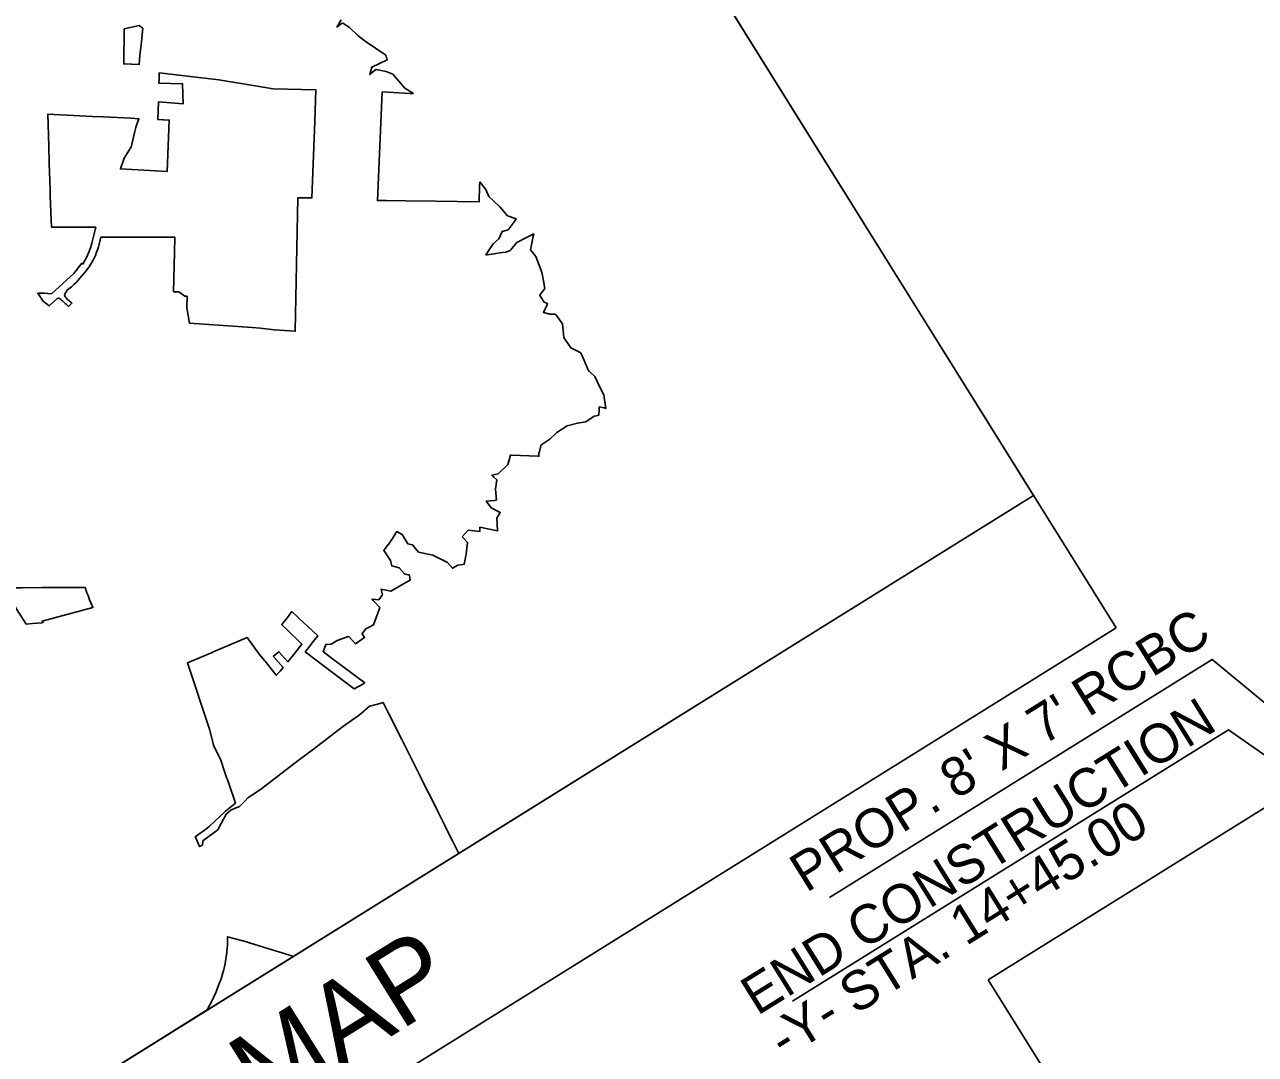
# Model space of a CAD drawing. Extents: x 2038094 to 2053858, y 751760 to 764312.
# Drawn here: x 2044647 to 2046307, y 758364 to 759754 of the extents above; entities that cross this region are included whole.
import ezdxf

# ---------------------------------------------------------------- set-up
doc = ezdxf.new("R2010")
doc.units = 0
for name, color, linetype in [('Old_Level_14', 7, 'Continuous'), ('Prop Shade Light', 7, 'Continuous'), ('Scratch_Level_1', 7, 'Continuous'), ('Sheet Clip Boundary CELL', 7, 'Continuous'), ('Sheet Title CELL', 7, 'Continuous')]:
    doc.layers.add(name, color=color, linetype=linetype)

msp = doc.modelspace()

# ---------------------------------------------------------------- linework, layer by layer
at = {"layer": 'Old_Level_14'}
for points in [[(2046763, 758471.6), (2046248.1, 758896.8), (2045732.1, 758575.3)], [(2046620.1, 758557.1), (2046270.1, 758802), (2045682.1, 758435.8)]]:
    msp.add_lwpolyline(points, dxfattribs=at)
at = {"layer": 'Prop Shade Light'}
for p, q in [((2045009, 758495.9), (2045232.3, 758635)), ((2044650.5, 758272.7), (2044893.1, 758423.7))]:
    msp.add_line(p, q, dxfattribs=at)
for points in [[(2045075.6, 759755.8), (2045067.8, 759750.3), (2045073.7, 759759.9)], [(2044805.2, 759740.4), (2044804.5, 759729.9), (2044802, 759712.2), (2044801.2, 759699.8), (2044780.4, 759700.4), (2044781, 759747.7), (2044801.3, 759752.4), (2044806, 759748.7), (2044805.2, 759740.4)], [(2045171.1, 759660.6), (2045159.3, 759667.9), (2045143.5, 759686.6), (2045134.1, 759690.3), (2045120.5, 759693), (2045113, 759686.9), (2045112.9, 759686.8), (2045112.1, 759686.2), (2045115, 759696.2), (2045135.7, 759705.8), (2045134.6, 759709.4), (2045134.5, 759709.5), (2045133.7, 759712.3), (2045105.8, 759731.2), (2045096.7, 759738.6), (2045084.6, 759750), (2045075.8, 759755.7)], [(2044865.5, 759371.1), (2044865.9, 759387), (2044862.7, 759387.1), (2044854.5, 759393), (2044848.5, 759393.1), (2044847.6, 759393.1), (2044848.9, 759446.1), (2044849.4, 759466.5), (2044749.6, 759466.8), (2044747.2, 759457.4), (2044746.2, 759453.5), (2044744.9, 759449.4), (2044743.8, 759446.4), (2044742.1, 759442.1), (2044739.9, 759437.4), (2044737.9, 759433.6), (2044735.7, 759429.8), (2044733.6, 759426.6), (2044731.6, 759423.8), (2044729.5, 759421.1), (2044718.6, 759408.3), (2044717.3, 759406.6), (2044715.6, 759405), (2044713.2, 759402.6), (2044710.1, 759399.8), (2044704.5, 759395.5), (2044700.3, 759389.5), (2044701.2, 759386.3), (2044702.8, 759384.6), (2044704.7, 759382.6), (2044706.8, 759380.7), (2044708.8, 759379), (2044710.5, 759377.6), (2044705.8, 759373.2), (2044703.2, 759375.6), (2044701.3, 759377.2), (2044700.1, 759378.4), (2044699.4, 759379), (2044698.5, 759379.8), (2044697.6, 759380.6), (2044696.8, 759381.2), (2044696.2, 759381.8), (2044695.8, 759382.2), (2044695.1, 759382.8), (2044694.4, 759383.4), (2044693.8, 759383.9), (2044693.6, 759384.1), (2044693.2, 759384.2), (2044693, 759384.3), (2044692.5, 759384.3), (2044692, 759384.3), (2044691.8, 759384.3), (2044691.4, 759384.1), (2044691.1, 759383.9), (2044690.8, 759383.7), (2044680, 759374), (2044671.9, 759380.4), (2044664.3, 759391.1), (2044669.7, 759391), (2044672.9, 759391), (2044683.1, 759390.3), (2044713, 759417.8), (2044723.9, 759431.5), (2044725.4, 759430.3), (2044728.1, 759435), (2044730.7, 759440.2), (2044733.3, 759446.3), (2044735.4, 759452.3), (2044737.2, 759458.6), (2044742.7, 759480.2), (2044683, 759480.2), (2044681.7, 759511.2), (2044681.3, 759522.3), (2044681, 759531.3), (2044680, 759565.9), (2044679.3, 759589.7), (2044678.9, 759604.2), (2044678, 759632.7), (2044738.1, 759629.7), (2044753, 759628.9), (2044790.4, 759627.2), (2044800.8, 759626.6), (2044799, 759621.3), (2044796.8, 759615.3), (2044796.5, 759614.5), (2044794.9, 759607.7), (2044790.5, 759588.1), (2044790.1, 759587.5), (2044781, 759573.3), (2044775.8, 759558.7), (2044823.4, 759556), (2044838.8, 759555.1), (2044841.8, 759624.6), (2044826.4, 759625.4), (2044827.3, 759649.5), (2044860.5, 759646.5), (2044859.8, 759673.8), (2044827.9, 759674.3), (2044828, 759679.4), (2044828.2, 759688.6)], [(2044828.2, 759688.6), (2044908.4, 759679.1), (2044963, 759669.9), (2044982.1, 759666.8), (2045039.5, 759665.5), (2045038, 759622.6), (2045034.2, 759519.6), (2045015.1, 759519.6), (2045011.6, 759339.8), (2044983.2, 759341.6), (2044965, 759343.9), (2044953.5, 759344.7), (2044869.1, 759350.6), (2044865.5, 759371.1)], [(2045260.4, 759541.4), (2045260.2, 759536.4), (2045259.6, 759514.3), (2045200.6, 759515.2), (2045160.4, 759515.7), (2045134.4, 759516.1), (2045122.5, 759516), (2045128.9, 759662.6), (2045166.5, 759660.6), (2045169.7, 759660.4), (2045171.1, 759660.6)], [(2045280.1, 759111.5), (2045280.2, 759111.5), (2045283, 759111.8), (2045281.9, 759126.8), (2045283.4, 759139.3), (2045279.7, 759142.9), (2045279.7, 759143), (2045277.1, 759145.5), (2045285.5, 759147.5), (2045297.4, 759158.9), (2045297.6, 759159.1), (2045298.4, 759159.8), (2045301.1, 759169.3), (2045301.9, 759172.3), (2045303.2, 759172.3), (2045339.3, 759171.1), (2045339.4, 759171), (2045340.4, 759171), (2045340.3, 759174.6), (2045340.9, 759177.4), (2045342.7, 759184.9), (2045342.9, 759185.9), (2045355, 759194.1), (2045364.5, 759203), (2045378.5, 759212.2), (2045392.2, 759215.8), (2045403.4, 759217.4), (2045414.9, 759224.9), (2045417.5, 759225.6), (2045419.1, 759226.1), (2045419.2, 759226.1), (2045421.2, 759226.7), (2045421.4, 759233.4), (2045421.4, 759235.1), (2045421.5, 759237.7), (2045428.1, 759236.2), (2045428.2, 759236.2), (2045430.7, 759235.6), (2045427.7, 759253.7), (2045422.6, 759264.1), (2045415.6, 759278.5), (2045408.6, 759285.5), (2045406.3, 759287.9), (2045404.7, 759292), (2045403.9, 759294), (2045400.3, 759302.5), (2045396.8, 759310.7), (2045383.4, 759317.5), (2045374, 759331.3), (2045372, 759349.6), (2045362.5, 759362.7), (2045354.9, 759362.8), (2045346.5, 759365.1), (2045346.3, 759365.1), (2045347.9, 759368.3), (2045348.2, 759368.9), (2045349.6, 759371.9), (2045349.8, 759372.4), (2045349.9, 759372.4), (2045352, 759377), (2045347.4, 759378.8), (2045342.4, 759386.5), (2045342.3, 759386.6), (2045341.9, 759387.2), (2045341.4, 759388.5), (2045345.3, 759393.5), (2045345.4, 759393.7), (2045348.2, 759397.4), (2045346.4, 759407.7), (2045345.1, 759414.9), (2045344.4, 759419.1), (2045343.4, 759421.6), (2045336.1, 759440.7), (2045331.2, 759446.9), (2045329.1, 759449.6), (2045332.2, 759465.5), (2045332.3, 759466.2), (2045333.3, 759471.2), (2045323.7, 759466.2), (2045310.3, 759459.3), (2045301.3, 759448.5), (2045295.7, 759446.3), (2045291.3, 759445.9), (2045284.7, 759445.2), (2045270.5, 759443), (2045270.3, 759443), (2045268.9, 759442.8), (2045278.4, 759457.7), (2045286.2, 759464.4), (2045290.7, 759474.2), (2045298.8, 759476.6), (2045307, 759487.4), (2045307, 759487.5), (2045309.8, 759491.2), (2045298, 759495.6), (2045287.7, 759507.6), (2045272.9, 759521.4), (2045268.7, 759530.9), (2045265.1, 759535.5), (2045260.4, 759541.4)], [(2045025, 758906.9), (2045054.9, 758884.6), (2045091.2, 758857.1), (2045097.8, 758860.7), (2045102.7, 758863.4), (2045105.5, 758865), (2045062, 758897.7), (2045049.8, 758907), (2045049.7, 758907), (2045049.5, 758907.2), (2045053, 758916.9), (2045054.6, 758917), (2045060.3, 758917.3), (2045068.2, 758922.4), (2045082.3, 758927.1), (2045083.9, 758927.7), (2045093, 758918), (2045104.9, 758926.2), (2045105, 758926.3), (2045105.1, 758926.3), (2045102.1, 758931.5), (2045102, 758931.6), (2045101.8, 758931.9), (2045106.7, 758938.3), (2045111.2, 758940.4), (2045117.3, 758943.3), (2045120.9, 758953.2), (2045121.8, 758955.6), (2045123.1, 758959.2), (2045125.9, 758967.1), (2045118.2, 758975.1), (2045118.2, 758975.1), (2045116.9, 758976.5), (2045115.3, 758978.1), (2045124.2, 758977.1), (2045128.9, 758983.6), (2045129, 758983.7), (2045129.4, 758984.2), (2045128.1, 758989.2), (2045127.5, 758991.5), (2045140.7, 758988.8), (2045164.1, 759002.6), (2045165.6, 759003.5), (2045165.8, 759003.5), (2045166.6, 759004), (2045165.6, 759010.6), (2045158.8, 759012.2), (2045151.6, 759020.5), (2045141.9, 759023.2), (2045140.2, 759030.5), (2045132.6, 759042), (2045132.5, 759042.1), (2045131.2, 759044), (2045137.1, 759051.7), (2045137.4, 759052.1), (2045139.2, 759054.7), (2045139.7, 759055.3), (2045142, 759058.8), (2045144.9, 759063.4), (2045146.3, 759065.7), (2045148.8, 759069.5), (2045155.9, 759065.6), (2045163.3, 759052.9), (2045169.7, 759051.3), (2045170.4, 759051.1), (2045173.9, 759046.6), (2045177.9, 759041.4), (2045197.2, 759037.7), (2045216.8, 759027.4), (2045223.7, 759019.8), (2045230.9, 759024.2), (2045237.6, 759025), (2045237.7, 759025), (2045239.7, 759025.2), (2045242.1, 759038.7), (2045242.1, 759038.9), (2045242.2, 759039.4), (2045244, 759054.7), (2045238.2, 759060.9), (2045236.8, 759062.3), (2045245.1, 759071.2), (2045257.1, 759069.7), (2045257.2, 759069.7), (2045260.6, 759069.3), (2045260.6, 759070.2), (2045260.7, 759075.2), (2045282.3, 759070.7), (2045282.4, 759070.6), (2045284.6, 759070.2), (2045283.5, 759088), (2045284.7, 759089.9), (2045285.1, 759090.5), (2045285.3, 759090.8), (2045288.1, 759095.2), (2045276.1, 759101.6), (2045272.5, 759106.3), (2045272.5, 759106.4), (2045269.3, 759110.4), (2045280.1, 759111.5)], [(2044699.2, 758994), (2044728.4, 758993.7), (2044730.8, 758986.8), (2044732.3, 758982.9), (2044734.4, 758977.4), (2044736.5, 758972.3), (2044738.8, 758966.7), (2044670.3, 758948.6), (2044671.5, 758946.6), (2044669.7, 758946.4), (2044657.5, 758945.2), (2044649, 758944.4), (2044636.4, 758964.4), (2044633.6, 758968.9), (2044632.5, 758970.5), (2044629.8, 758974.9), (2044621.6, 758987.9), (2044618.1, 758993.5), (2044640.4, 758993.5), (2044643.9, 758993.5), (2044669.7, 758994.1), (2044699.2, 758994)], [(2044911.2, 758760.8), (2044901.3, 758781.1), (2044899.4, 758788.8), (2044896, 758802.5), (2044866.3, 758892.2), (2044899.4, 758906), (2044900.1, 758906.4), (2044946.7, 758926.6), (2044962.9, 758903.9), (2044970.2, 758895.3), (2044970.9, 758894.5), (2044986, 758875.5), (2044986.1, 758875.4), (2044991.3, 758881.1), (2044995.3, 758885.9), (2044995.2, 758886), (2044982.1, 758901), (2044982.5, 758901.3), (2044989.7, 758907.2), (2045001.8, 758893.6), (2045003.5, 758895.6), (2045011.4, 758905.7), (2045012.6, 758907.2), (2045019.2, 758915.5), (2045020.6, 758917.2), (2044999.4, 758937.9), (2044993.5, 758943.6), (2044993.8, 758944.1), (2045001.1, 758953.5), (2045007.2, 758961.4), (2045016.6, 758952.7), (2045034.8, 758935.6), (2045042, 758928.8), (2045034.2, 758918.7), (2045033.4, 758917.7), (2045029.5, 758912.6), (2045025, 758906.9)], [(2045232.3, 758635), (2045228.3, 758643.1), (2045223.8, 758652), (2045218.9, 758661.6), (2045213.4, 758672.7), (2045204.9, 758689.6), (2045195.7, 758708), (2045191.4, 758716.9), (2045190.7, 758717.9), (2045181.3, 758736.7), (2045169.3, 758760.7), (2045155.2, 758788.8), (2045138, 758823.3), (2045130.8, 758837.6), (2045130.2, 758838.7), (2045127.4, 758837.9), (2045114.1, 758834.3), (2045111.7, 758833.6), (2045100.5, 758824), (2045096, 758820.2), (2045087.5, 758814.2), (2045075.6, 758805.9), (2045036.5, 758775.9), (2045015.8, 758760.2), (2044966.7, 758722.8), (2044961.9, 758719.6), (2044947.8, 758710.1), (2044944, 758706.1), (2044936.4, 758698.2), (2044929.9, 758695.5), (2044924.8, 758693.3), (2044918.7, 758688.2), (2044911.8, 758675.4), (2044907.1, 758666.8), (2044902.3, 758663.3), (2044900.7, 758662.1), (2044887, 758651.8), (2044886.5, 758646.3), (2044882.7, 758644.3), (2044881.3, 758647.4), (2044880, 758650.5), (2044877.6, 758656), (2044877.5, 758656.2), (2044876.9, 758657.5), (2044889.4, 758666.3), (2044890.6, 758667.2), (2044895.8, 758671.4), (2044917.7, 758692.1), (2044919.7, 758693.8), (2044930.9, 758702.8), (2044921.5, 758730.9), (2044919.7, 758735.6), (2044919, 758737.5), (2044916.1, 758745.6), (2044911.2, 758760.8)], [(2044893.1, 758423.7), (2044899.4, 758436.4), (2044901.9, 758441.6), (2044904.8, 758448.1), (2044906, 758450.9), (2044907.4, 758454.4), (2044909.6, 758460.4), (2044911.6, 758465.9), (2044912.6, 758469.1), (2044913.5, 758472.2), (2044913.7, 758472.7), (2044914.8, 758476.6), (2044915.6, 758480), (2044916.5, 758484.2), (2044917.9, 758492), (2044918.4, 758495.4), (2044919.2, 758501.4), (2044919.4, 758503.1), (2044919.7, 758507), (2044920.1, 758511.1), (2044920.2, 758522.5), (2044939.2, 758517.5), (2044940.5, 758517.2)], [(2044940.5, 758517.2), (2044941.6, 758516.9), (2044957, 758512), (2044986.5, 758503), (2044995.2, 758500.4), (2045008, 758496.4), (2045009, 758495.9)]]:
    msp.add_lwpolyline(points, dxfattribs=at)
at = {"layer": 'Scratch_Level_1'}
msp.add_lwpolyline([(2045946.3, 758464.5), (2046501.4, 757573.2), (2047629.6, 758276), (2047220.5, 759009), (2047136.3, 758956.5), (2047077, 759051.7), (2046934.2, 758962.7), (2046881.6, 759047.1)], close=True, dxfattribs=at)
at = {"layer": 'Sheet Clip Boundary CELL'}
msp.add_lwpolyline([(2043662.2, 757657.1), (2046007.5, 759117.9), (2044949.5, 760816.6), (2042604.1, 759355.8)], close=True, dxfattribs=at)
at = {"layer": 'Sheet Title CELL'}
for p, q in [((2046118.7, 758939.3), (2044949.5, 760816.6)), ((2043662.2, 757657.1), (2046007.5, 759117.9)), ((2043773.4, 757478.5), (2046118.7, 758939.3))]:
    msp.add_line(p, q, dxfattribs=at)

# ---------------------------------------------------------------- texts
at = {"layer": 'Old_Level_14'}
for s, p in [("PROP. 8' X 7' RCBC", (2045700.8, 758581.3)), ('END CONSTRUCTION', (2045634.8, 758415.3)), ('-Y- STA. 14+45.00', (2045671.2, 758356.9))]:
    msp.add_text(s, height=52.501, rotation=31.918, dxfattribs=at).set_placement(p)
at = {"layer": 'Sheet Title CELL'}
msp.add_text('VICINITY MAP', height=108, rotation=31.9164, dxfattribs=at).set_placement((2044417.7, 757937.4))

doc.saveas('drawing.dxf')
